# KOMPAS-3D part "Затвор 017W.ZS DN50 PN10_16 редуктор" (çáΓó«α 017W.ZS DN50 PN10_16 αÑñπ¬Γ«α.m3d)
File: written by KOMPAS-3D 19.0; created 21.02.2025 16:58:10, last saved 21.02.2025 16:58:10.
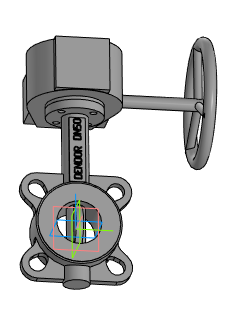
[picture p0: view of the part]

Document properties: Автор: Евгений; Полное имя файла: Затвор 017W.ZS DN50 PN10_16 редуктор.a3d

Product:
- Part/product: Затвор 017W.ZS DN50 PN10_16 редуктор
    Масса: 9.08729

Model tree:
1. Операция без истории:1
